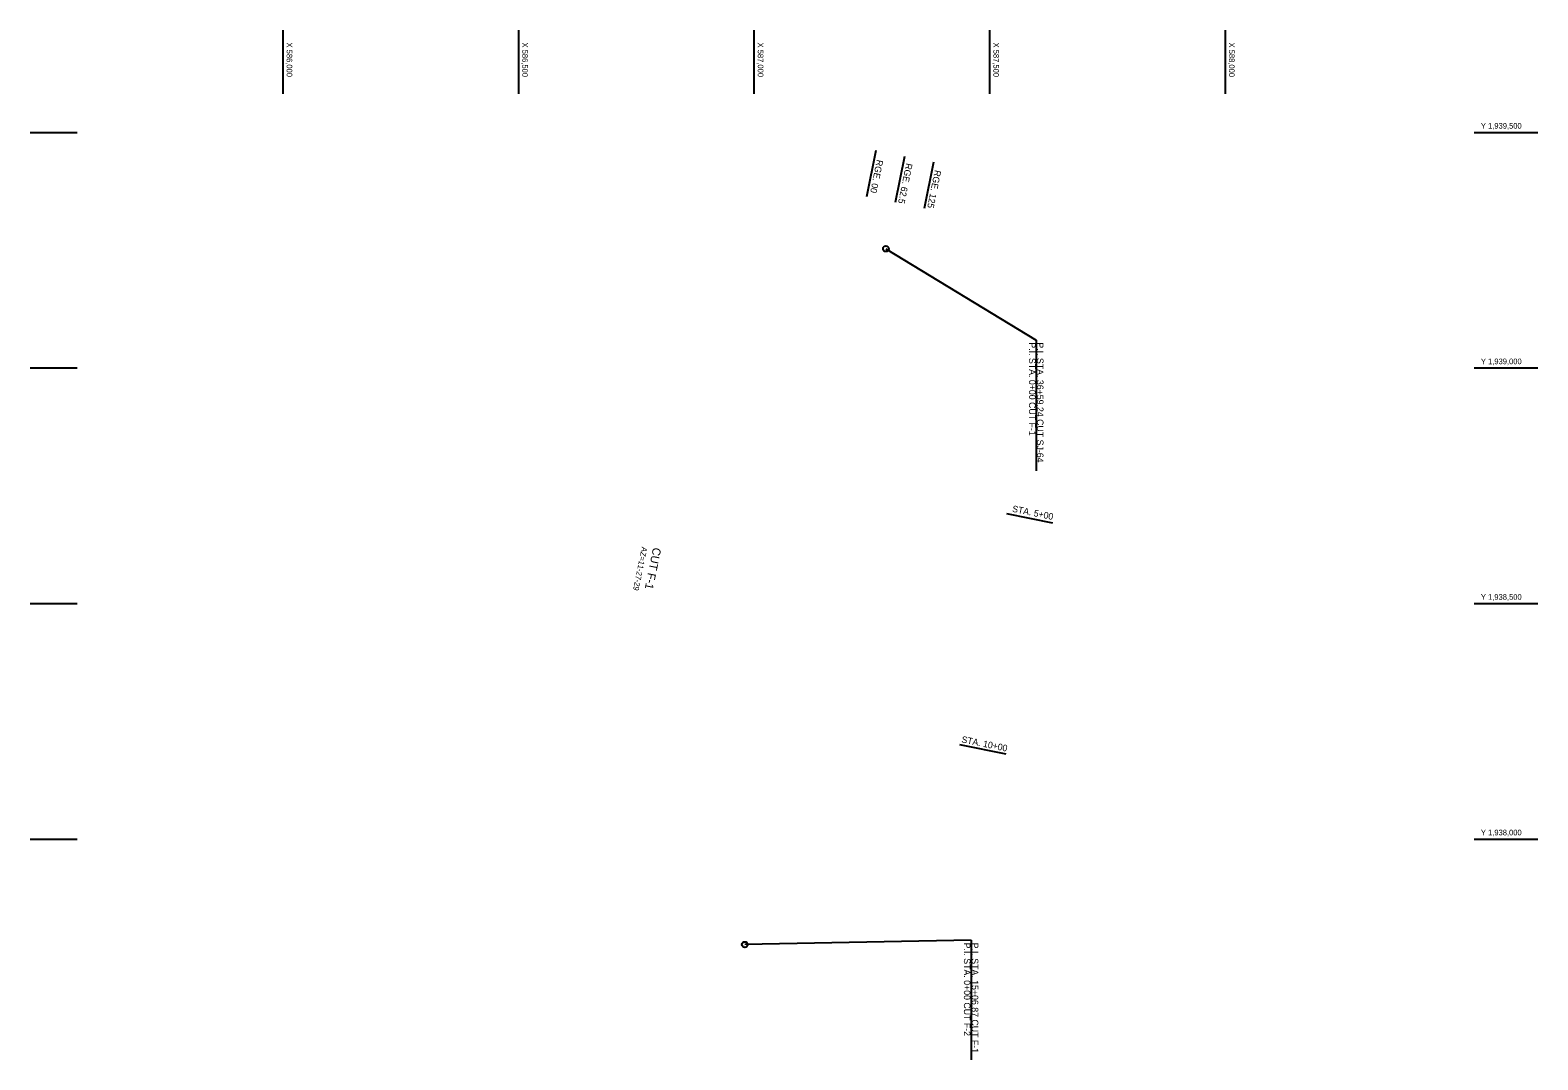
# Model space of a CAD drawing. Extents: x 585464 to 588664, y 1935616 to 1939717.
# Drawn here: x 585464 to 588664, y 1937531 to 1939717 of the extents above; entities that cross this region are included whole.
import ezdxf

# ---------------------------------------------------------------- set-up
doc = ezdxf.new("R2010")
doc.units = 0
for name, color, linetype in [('V-ANNO-KEYN', 7, 'Continuous'), ('V-ANNO-NPLT', 7, 'Continuous'), ('V-ANNO-PATT', 7, 'Continuous'), ('V-ANNO-SYMB', 7, 'Continuous'), ('V-ANNO-TEXT', 7, 'Continuous')]:
    doc.layers.add(name, color=color, linetype=linetype)

msp = doc.modelspace()

# ---------------------------------------------------------------- linework, layer by layer
at = {"layer": 'V-ANNO-NPLT'}
for p, q in [((587279.9, 1939253.1), (587599.1, 1939059.2)), ((587599.1, 1939059.2), (587599.1, 1938781.6)), ((587535.8, 1938691.1), (587633.8, 1938671.2)), ((587436.5, 1938201), (587534.5, 1938181.2)), ((587460.8, 1937785.4), (586980.5, 1937776.3)), ((587460.8, 1937785.4), (587460.8, 1937531.5))]:
    msp.add_line(p, q, dxfattribs=at)
for centre in [(587279.9, 1939253.1), (586980.5, 1937776.3)]:
    msp.add_circle(centre, 6, dxfattribs=at)
at = {"layer": 'V-ANNO-PATT'}
for p, q in [((587258.3, 1939461.5), (587238.5, 1939363.5)), ((587319.6, 1939449.1), (587299.7, 1939351.1)), ((587380.8, 1939436.7), (587361, 1939338.7))]:
    msp.add_line(p, q, dxfattribs=at)
at = {"layer": 'V-ANNO-TEXT'}
for p, q in [((586000, 1939717.1), (586000, 1939582.1)), ((586500, 1939717.1), (586500, 1939582.1)), ((587000, 1939717.1), (587000, 1939582.1)), ((587500, 1939717.1), (587500, 1939582.1)), ((588000, 1939717.1), (588000, 1939582.1)), ((585463.7, 1939500), (585563.7, 1939500)), ((588528.7, 1939500), (588663.7, 1939500)), ((585463.7, 1939000), (585563.7, 1939000)), ((588528.7, 1939000), (588663.7, 1939000)), ((585463.7, 1938500), (585563.7, 1938500)), ((588528.7, 1938500), (588663.7, 1938500)), ((585463.7, 1938000), (585563.7, 1938000)), ((588528.7, 1938000), (588663.7, 1938000))]:
    msp.add_line(p, q, dxfattribs=at)

# ---------------------------------------------------------------- texts
at = {"layer": 'V-ANNO-KEYN'}
for s, p in [('X 586,000', (586008, 1939690.8)), ('X 586,500', (586508, 1939690.8)), ('X 587,000', (587008, 1939690.7)), ('X 587,500', (587508, 1939690.7)), ('X 588,000', (588008, 1939690.7))]:
    msp.add_text(s, height=12, rotation=270, dxfattribs=at).set_placement(p)
for s, p in [('Y 1,939,500', (588542.8, 1939508)), ('Y 1,939,000', (588542.8, 1939008)), ('Y 1,938,500', (588542.8, 1938508)), ('Y 1,938,000', (588542.8, 1938008))]:
    msp.add_text(s, height=12, dxfattribs=at).set_placement(p)
at = {"layer": 'V-ANNO-NPLT'}
for s, rotation, p in [('P.I. STA. 0+00 CUT F-1', 270, (587583.8, 1939054.4)), ('P.I. STA. 36+59.24 CUT SJ-64', 270, (587600.5, 1939054.4)), ('STA. 5+00', 348.5419, (587547.1, 1938694.9)), ('STA. 10+00', 348.5419, (587439.5, 1938205.3)), ('P.I. STA. 0+00 CUT F-2', 270, (587445.5, 1937780.2)), ('P.I. STA. 15+06.87 CUT F-1', 270, (587462.2, 1937780.2))]:
    msp.add_text(s, height=13.92, rotation=rotation, dxfattribs=at).set_placement(p)
at = {"layer": 'V-ANNO-PATT'}
for s, p in [('RGE. 00', (587260.7, 1939442.9)), ('RGE. 62.5', (587323, 1939435.5)), ('RGE. 125', (587383.8, 1939420.9))]:
    msp.add_text(s, height=13.92, rotation=258.5419, dxfattribs=at).set_placement(p)
at = {"layer": 'V-ANNO-SYMB'}
for s, height, p in [('AZ=11-27-29', 12, (586762, 1938621.1)), ('CUT F-1', 17.52, (586786, 1938619.9))]:
    msp.add_text(s, height=height, rotation=258.5419, dxfattribs=at).set_placement(p)

doc.saveas('drawing.dxf')
